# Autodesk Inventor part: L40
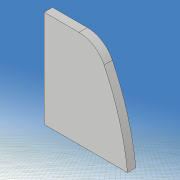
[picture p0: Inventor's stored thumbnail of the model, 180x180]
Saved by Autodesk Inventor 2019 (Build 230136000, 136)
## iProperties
Created: 2021-05
Part Number: L40
Material: 一般
Document SubType Name: Modeling
Designer: kikut
Density: 1 g/cm^3
Appearance: 既定
Mass: 0.00934248 g
Surface Area: 0.426451 cm^2
Volume: 0.00934248 cm^3
Author: kikut
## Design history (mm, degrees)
sketch "スケッチ1"
  geometry: L1 (80, 60)-(-80, 60); L2 (-80, 60)-(-80, -60); L3 (-80, -60)-(80, -60); L4 (80, -60)-(80, 60); L5 (80, 60)-(-80, -60); L6 (-80, 60)-(80, -60); 1 further point
  constraints: 12 end point, 2 midpoint, 2 parallel, 1 horizontal, 1 perpendicular
  dimensions: "d0" = 160 distance of L2.end L3.end; "d1" = 120 distance of L1.end L2.end
extrude "押し出し1" new body sketch "スケッチ1" stored distance "d2" = 0.6; taper "d3" = 0 deg
sketch "スケッチ2"
  geometry: L1 (-140, 0)-(140, 0) reference; L2 (0, -54)-(20, -30); L3 (0, 54)-(20, 30); L4 (0, -3)-(6.514, -3); L5 (6.514, -3)-(16, -6); L6 (16, -6)-(24, -3); L7 (24, -3)-(33.716, -3); L8 (0, 3)-(6.514, 3); L9 (6.514, 3)-(16, 6); L10 (16, 6)-(24, 3); L11 (24, 3)-(33.716, 3); L12 (0, -98)-(0, 98) reference; L13 (-100, -70)-(100, -70); L14 (100, -70)-(100, 70); L15 (100, 70)-(-100, 70); L16 (-100, 70)-(-100, -70); L17 (-100, -70)-(100, 70); L18 (100, -70)-(-100, 70); A1 r 60 centre (54.312, 28.5) between (0, 54) and (0, 3); A2 r 60 centre (54.312, -28.5) between (0, -3) and (0, -54); A3 r 18.111 centre (18, -12) between (20, -30) and (33.716, -3); A4 r 18.111 centre (18, 12) between (33.716, 3) and (20, 30); 1 further point
  constraints: 32 end point, 8 point on circle, 8 symmetric about line, 4 centre point, 3 horizontal, 2 collinear, 2 midpoint, 2 parallel, 1 perpendicular
  dimensions: "d5" = 60 radius of A1; "d6" = 6 distance of L8.start L4.start; "d7" = 108 distance of L3.start L2.start; "d8" = 0 horizontal distance of L3.start L8.start; "d9" = 60 distance of L3.end L2.end; "d10" = 0 horizontal distance of point (0, 0) L3.start; "d11" = 20 horizontal distance of L3.start L3.end; "d12" = 24 distance of A4.centre A3.centre; "d13" = 6 distance of L11.end L7.end; "d14" = 12 distance of L9.end L5.end; "d15" = 16 distance from line of L12 L5.end; "d16" = 24 distance from line of L6.end L12; "d17" = 200 distance of L14.end L15.end; "d18" = 140 distance of L15.end L13.start; "d30" = 18 distance from line of L12 A4.centre
extrude "押し出し2" cut sketch "スケッチ2" stored distance "d19" = 10; taper "d20" = 0 deg
sketch "スケッチ3"
  geometry: L1 (49.705, -17.97)-(33.948, -15.191); L2 (33.948, -15.191)-(34.295, -13.222); L3 (34.295, -13.222)-(50.052, -16); L4 (50.052, -16)-(49.705, -17.97); L5 (49.705, -17.97)-(34.295, -13.222); L6 (33.948, -15.191)-(50.052, -16); L7 (50.052, 16)-(34.295, 13.222); L8 (34.295, 13.222)-(33.948, 15.191); L9 (33.948, 15.191)-(49.705, 17.97); L10 (49.705, 17.97)-(50.052, 16); L11 (50.052, 16)-(33.948, 15.191); L12 (34.295, 13.222)-(49.705, 17.97); L13 (-112, 0)-(112, 0) reference; L14 (0, -84)-(0, 84) reference; 3 further points
  constraints: 24 end point, 4 midpoint, 4 parallel, 2 perpendicular, 2 symmetric about line
  dimensions: "d21" = 2 distance of L3.end L1.start; "d22" = 2 distance of L9.end L7.start; "d23" = 16 distance of L8.end L9.end; "d24" = 42 distance from line of L14 point (42, 15.596); "d26" = 10 deg angle of L7 L13; "d62" = 16 distance from line of L3.end L13
extrude "押し出し3" join sketch "スケッチ3" distance "d27" = 0.6; taper "d28" = 0 deg
fillet "フィレット1" dims "d31" = 2
fillet "フィレット2" dims "d32" = 1
sketch "スケッチ7"
  geometry: L1 (-20, 60)-(80, 60); L2 (80, 60)-(80, -60); L3 (80, -60)-(-20, -60); L4 (-20, -60)-(-20, 60); L5 (0, -82.207)-(0, 85.793) reference; L6 (-40, 0)-(100, 0) reference; L7 (30, 0)-(37, 0); L8 (37, 0)-(37, -10); L9 (37, -10)-(30, -10); L10 (30, -10)-(30, 0); 1 further point
  constraints: 16 end point, 4 parallel, 2 horizontal, 2 perpendicular, 1 other
  dimensions: "d80" = 120 distance of L3.end L1.start; "d81" = 20 distance between parallel lines of L5 L4; "d82" = 100 distance of L1.start L1.end; "d84" = 7 distance of L8.end L9.end; "d85" = 10 distance of L7.end L8.end; "d86" = 50 distance between parallel lines of L4 L10; "d93" = 50 distance between parallel lines of L3 L9
extrude "押し出し5" cut sketch "スケッチ7" stored distance "d87" = 10; taper "d88" = 0 deg
node "ソリッド1"
